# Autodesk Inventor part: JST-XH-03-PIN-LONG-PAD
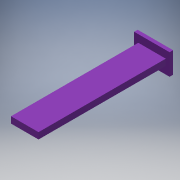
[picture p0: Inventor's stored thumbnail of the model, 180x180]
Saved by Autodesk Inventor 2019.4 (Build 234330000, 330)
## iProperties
Created: 2019-11
Part Number: JST-XH-03-PIN-LONG-PAD
Material: Generic
Document SubType Name: Modeling
Designer: Willist
Density: 1 g/cm^3
Appearance: JST-XH-03-PACKAGE-LONG-PAD, JST-XH-03-PIN-LONG-PAD
Author: Willist
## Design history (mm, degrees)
sketch "JST-XH-03-PACKAGE-LONG-PAD, JST-XH-03-PIN-LONG-PAD_21"
  geometry: L1 (-4.95, 3.519)-(5.077, 3.519); L2 (5.077, 3.519)-(5.077, -2.485); L3 (5.077, -2.485)-(-4.95, -2.485); L4 (-4.95, -2.485)-(-4.95, 3.519)
  constraints: 8 end point
extrude "Extrusion1" join sketch "JST-XH-03-PACKAGE-LONG-PAD, JST-XH-03-PIN-LONG-PAD_21" distance "d0" = 1; taper "d1" = 0 deg
sketch "Sketch2"
  geometry: L1 (-3.78, 1.413)-(4.007, 1.413); L2 (4.007, 1.413)-(4.007, -0.378); L3 (4.007, -0.378)-(-3.78, -0.378); L4 (-3.78, -0.378)-(-3.78, 1.413); L5 (-3.78, 1.413)-(4.007, -0.378); L6 (4.007, 1.413)-(-3.78, -0.378); 2 further points
  constraints: 12 end point, 2 midpoint, 2 parallel, 1 horizontal, 1 perpendicular
extrude "Extrusion2" join sketch "Sketch2" distance "d2" = 36; taper "d3" = 0 deg
body "Solid1"
